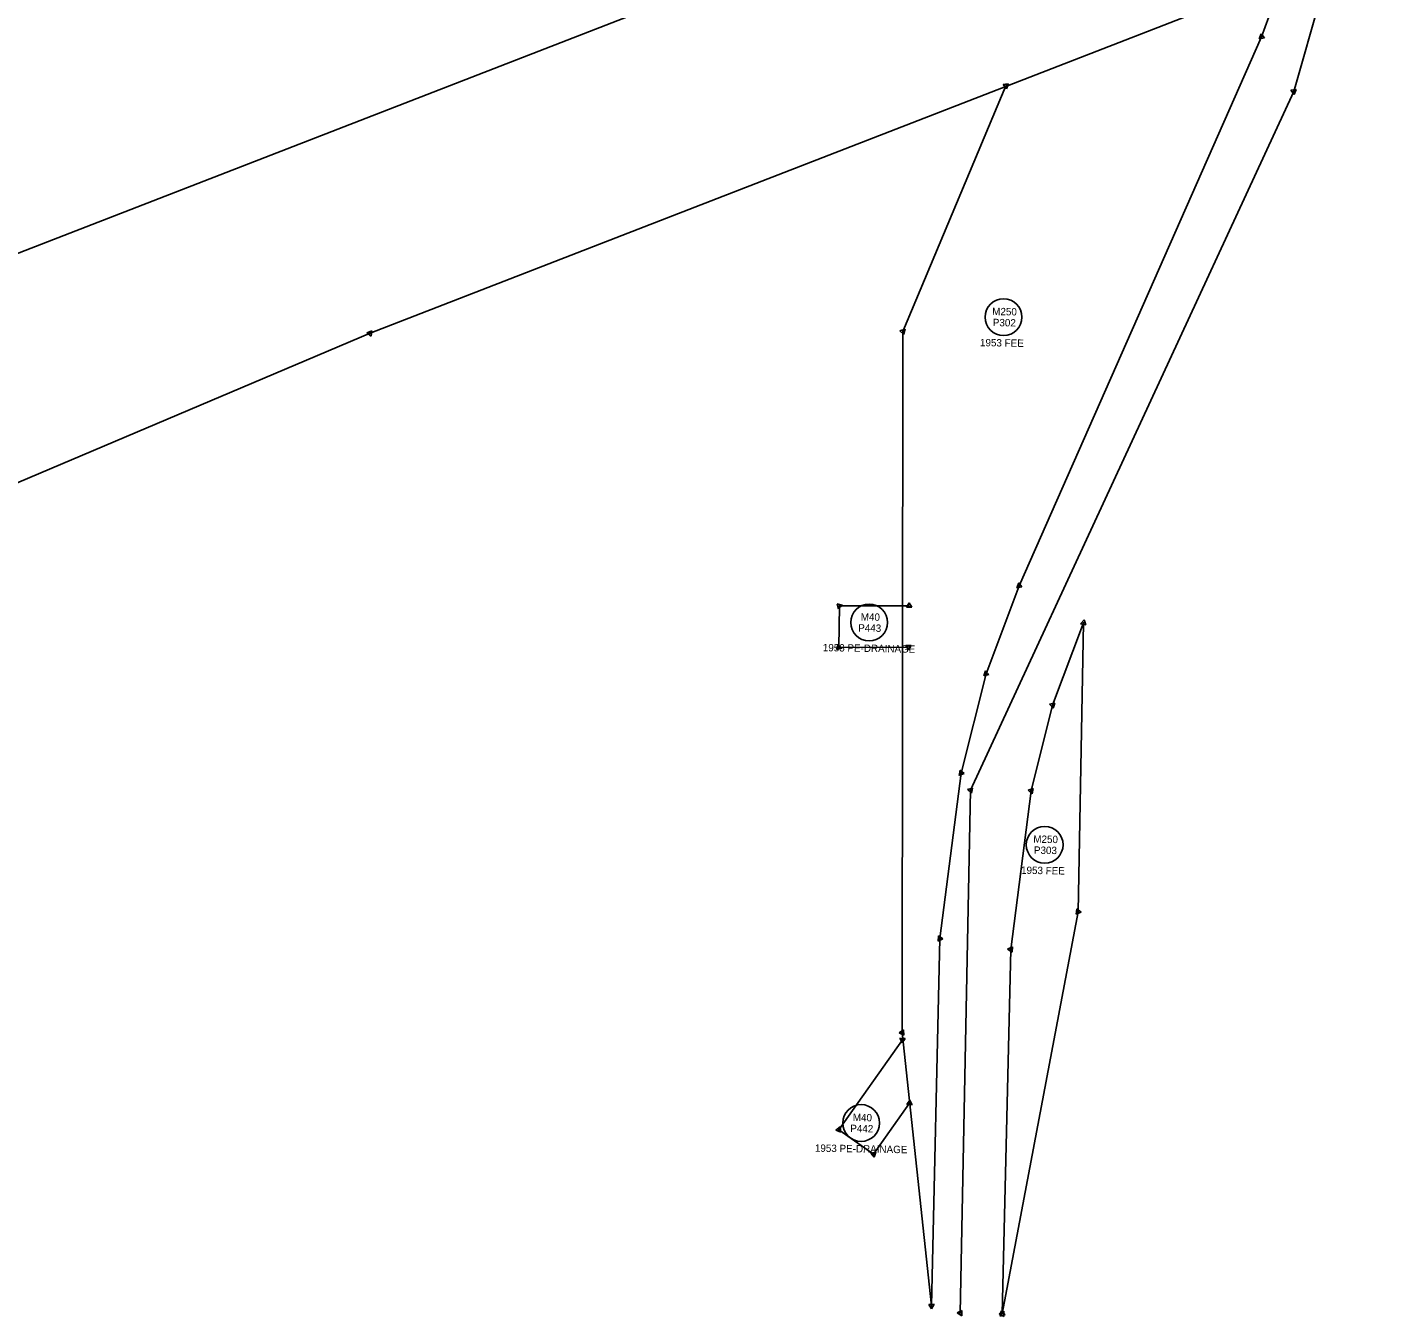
# Model space of a CAD drawing. Extents: x 325018 to 414989, y 1517547 to 1550415.
# Drawn here: x 389679 to 390658, y 1519044 to 1519963 of the extents above; entities that cross this region are included whole.
import ezdxf

# ---------------------------------------------------------------- set-up
doc = ezdxf.new("R2010")
doc.units = 0
for name, color, linetype in [('Level 56', 7, 'Continuous'), ('MEE', 7, 'Continuous'), ('MHB', 7, 'Continuous'), ('MHBWOA', 7, 'Continuous'), ('MRBL1', 7, 'Continuous'), ('MRBL2', 7, 'Continuous')]:
    doc.layers.add(name, color=color, linetype=linetype)

msp = doc.modelspace()

# ---------------------------------------------------------------- linework, layer by layer
at = {"layer": 'Level 56'}
for centre in [(390374.96, 1519756.85), (390279.09, 1519539.04), (390404.25, 1519380.53), (390273.44, 1519182.07)]:
    msp.add_circle(centre, 13.12, dxfattribs=at)
at = {"layer": 'MEE'}
for p, q in [((390257.53, 1519521.27), (390257.96, 1519550.82)), ((390257.96, 1519550.82), (390307.62, 1519551)), ((390307.19, 1519521.46), (390257.53, 1519521.27)), ((390257.64, 1519177.28), (390302.91, 1519241.39)), ((390308.02, 1519196.28), (390282.29, 1519159.79)), ((390282.29, 1519159.79), (390257.64, 1519177.28))]:
    msp.add_line(p, q, dxfattribs=at)
for points in [[(390257.39, 1519548.71), (390256.43, 1519552.37)], [(390256.43, 1519552.37), (390260.08, 1519551.37)], [(390260.08, 1519551.37), (390257.39, 1519548.71)], [(390305.74, 1519549.9), (390307.61, 1519553.18)], [(390309.51, 1519549.91), (390305.74, 1519549.9)], [(390307.61, 1519553.18), (390309.51, 1519549.91)], [(390255.98, 1519519.74), (390256.98, 1519523.39)], [(390259.63, 1519520.7), (390255.98, 1519519.74)], [(390256.98, 1519523.39), (390259.63, 1519520.7)], [(390305.29, 1519522.54), (390309.07, 1519522.56)], [(390307.19, 1519519.28), (390305.29, 1519522.54)], [(390309.07, 1519522.56), (390307.19, 1519519.28)], [(390302.71, 1519239.22), (390301.13, 1519242.65)], [(390301.13, 1519242.65), (390304.89, 1519242.31)], [(390304.89, 1519242.31), (390302.71, 1519239.22)], [(390306.04, 1519195.37), (390308.21, 1519198.46)], [(390309.8, 1519195.03), (390306.04, 1519195.37)], [(390308.21, 1519198.46), (390309.8, 1519195.03)], [(390255.49, 1519176.91), (390258.39, 1519179.32)], [(390259.03, 1519175.6), (390255.49, 1519176.91)], [(390258.39, 1519179.32), (390259.03, 1519175.6)], [(390280.25, 1519160.54), (390283.97, 1519161.18)], [(390282.66, 1519157.64), (390280.25, 1519160.54)], [(390283.97, 1519161.18), (390282.66, 1519157.64)]]:
    msp.add_lwpolyline(points, dxfattribs=at)
for centre, radius in [((390257.96, 1519550.82), 0.227), ((390307.62, 1519551), 1.09), ((390257.53, 1519521.27), 0.227), ((390307.18, 1519521.46), 1.09), ((390302.91, 1519241.4), 1.09), ((390308.02, 1519196.28), 1.09), ((390257.64, 1519177.28), 0.227), ((390282.29, 1519159.79), 0.227)]:
    msp.add_circle(centre, radius, dxfattribs=at)
at = {"layer": 'MHB'}
for p, q in [((390573.98, 1519998.09), (390558.88, 1519956.76)), ((390558.88, 1519956.76), (390386.02, 1519565.22)), ((390303.25, 1519746.6), (390376.69, 1519921.84)), ((390302.64, 1519246.6), (390303.25, 1519746.6)), ((390386.02, 1519565.22), (390362.48, 1519502.49)), ((390409.89, 1519480.06), (390431.94, 1519538.71)), ((390431.94, 1519538.71), (390428.06, 1519332.74)), ((390362.48, 1519502.49), (390344.74, 1519431.68)), ((390394.58, 1519418.95), (390409.89, 1519480.06)), ((390344.74, 1519431.68), (390329.58, 1519313.65)), ((390380.05, 1519305.88), (390394.58, 1519418.95)), ((390428.06, 1519332.74), (390374.06, 1519045.95)), ((390329.58, 1519313.65), (390323.54, 1519051.72)), ((390374.06, 1519045.95), (390380.05, 1519305.88)), ((390323.54, 1519051.72), (390302.64, 1519246.6))]:
    msp.add_line(p, q, dxfattribs=at)
for points in [[(390557.16, 1519955.42), (390558.57, 1519958.92)], [(390558.57, 1519958.92), (390560.9, 1519955.95)], [(390560.9, 1519955.95), (390557.16, 1519955.42)], [(390374.68, 1519922.68), (390378.43, 1519923.16)], [(390376.97, 1519919.67), (390374.68, 1519922.68)], [(390378.43, 1519923.16), (390376.97, 1519919.67)], [(390301.12, 1519747.03), (390304.7, 1519748.24)], [(390303.95, 1519744.53), (390301.12, 1519747.03)], [(390304.7, 1519748.24), (390303.95, 1519744.53)], [(390384.3, 1519563.88), (390385.73, 1519567.38)], [(390385.73, 1519567.38), (390388.04, 1519564.4)], [(390388.04, 1519564.4), (390384.3, 1519563.88)], [(390429.87, 1519537.99), (390432.34, 1519540.85)], [(390433.59, 1519537.28), (390429.87, 1519537.99)], [(390432.34, 1519540.85), (390433.59, 1519537.28)], [(390360.88, 1519501.01), (390362, 1519504.62)], [(390364.56, 1519501.84), (390360.88, 1519501.01)], [(390362, 1519504.62), (390364.56, 1519501.84)], [(390407.82, 1519480.71), (390411.5, 1519481.54)], [(390410.38, 1519477.93), (390407.82, 1519480.71)], [(390411.5, 1519481.54), (390410.38, 1519477.93)], [(390343.31, 1519430.03), (390344.01, 1519433.74)], [(390346.88, 1519431.28), (390343.31, 1519430.03)], [(390344.01, 1519433.74), (390346.88, 1519431.28)], [(390392.44, 1519419.36), (390396, 1519420.61)], [(390395.3, 1519416.89), (390392.44, 1519419.36)], [(390396, 1519420.61), (390395.3, 1519416.89)], [(390426.78, 1519330.98), (390427.16, 1519334.74)], [(390430.22, 1519332.52), (390426.78, 1519330.98)], [(390427.16, 1519334.74), (390430.22, 1519332.52)], [(390328.34, 1519311.85), (390328.63, 1519315.62)], [(390331.75, 1519313.49), (390328.34, 1519311.85)], [(390328.63, 1519315.62), (390331.75, 1519313.49)], [(390377.88, 1519306.05), (390381.29, 1519307.68)], [(390381, 1519303.92), (390377.88, 1519306.05)], [(390381.29, 1519307.68), (390381, 1519303.92)], [(390300.47, 1519246.49), (390303.64, 1519248.55)], [(390303.83, 1519244.77), (390300.47, 1519246.49)], [(390303.64, 1519248.55), (390303.83, 1519244.77)], [(390321.61, 1519052.73), (390325.38, 1519052.89)], [(390323.63, 1519049.54), (390321.61, 1519052.73)], [(390325.38, 1519052.89), (390323.63, 1519049.54)], [(390371.89, 1519046), (390375.2, 1519047.81)], [(390375.11, 1519044.04), (390371.89, 1519046)], [(390372.64, 1519044.3), (390373.34, 1519048.01)], [(390373.34, 1519048.01), (390376.2, 1519045.55)], [(390375.2, 1519047.81), (390375.11, 1519044.04)], [(390376.2, 1519045.55), (390372.64, 1519044.3)]]:
    msp.add_lwpolyline(points, dxfattribs=at)
for centre, radius in [((390558.88, 1519956.76), 0.227), ((390376.69, 1519921.84), 1.09), ((390303.25, 1519746.6), 0.227), ((390386.02, 1519565.22), 0.227), ((390431.94, 1519538.71), 0.227), ((390362.48, 1519502.49), 0.227), ((390409.89, 1519480.06), 0.227), ((390344.74, 1519431.68), 0.227), ((390394.58, 1519418.95), 0.227), ((390428.06, 1519332.74), 0.227), ((390329.58, 1519313.65), 0.227), ((390380.05, 1519305.88), 0.227), ((390302.64, 1519246.6), 0.227), ((390323.54, 1519051.72), 0.227), ((390374.06, 1519045.95), 1.09), ((390374.06, 1519045.95), 1.09)]:
    msp.add_circle(centre, radius, dxfattribs=at)
at = {"layer": 'MHBWOA'}
for p, q in [((390573.98, 1519998.09), (389923.35, 1519745.33)), ((389923.35, 1519745.33), (389462.55, 1519549.87))]:
    msp.add_line(p, q, dxfattribs=at)
for points in [[(389921.19, 1519745.64), (389924.69, 1519747.06)], [(389924.17, 1519743.32), (389921.19, 1519745.64)], [(389924.69, 1519747.06), (389924.17, 1519743.32)]]:
    msp.add_lwpolyline(points, dxfattribs=at)
msp.add_circle((389923.35, 1519745.33), 0.227, dxfattribs=at)
at = {"layer": 'MRBL1'}
msp.add_line((389440.86, 1519712.45), (390657.94, 1520185.18), dxfattribs=at)
at = {"layer": 'MRBL2'}
for p, q in [((390581.83, 1519917.84), (390657.94, 1520185.18)), ((390351.43, 1519419.36), (390581.83, 1519917.84)), ((390344.07, 1519046.54), (390351.43, 1519419.36))]:
    msp.add_line(p, q, dxfattribs=at)
for points in [[(390579.79, 1519918.6), (390583.52, 1519919.23)], [(390582.2, 1519915.69), (390579.79, 1519918.6)], [(390583.52, 1519919.23), (390582.2, 1519915.69)], [(390349.31, 1519419.85), (390352.92, 1519420.96)], [(390352.08, 1519417.27), (390349.31, 1519419.85)], [(390352.92, 1519420.96), (390352.08, 1519417.27)], [(390341.89, 1519046.59), (390345.2, 1519048.41)], [(390345.13, 1519044.63), (390341.89, 1519046.59)], [(390345.2, 1519048.41), (390345.13, 1519044.63)]]:
    msp.add_lwpolyline(points, dxfattribs=at)
for centre, radius in [((390581.83, 1519917.84), 0.227), ((390351.43, 1519419.36), 0.227), ((390344.07, 1519046.55), 1.09)]:
    msp.add_circle(centre, radius, dxfattribs=at)

# ---------------------------------------------------------------- texts
at = {"layer": 'Level 56'}
for s, height, p in [('M250', 5.249, (390366.84, 1519758.3)), ('P302', 5.249, (390367.26, 1519750.42)), ('1953 FEE', 5.249, (390358.11, 1519736.13)), ('M40', 5.249, (390273.13, 1519540.46)), ('P443', 5.249, (390271.32, 1519532.61)), ('1953 PE-DRAINAGE', 5.2493, (390246.08, 1519518.6)), ('M250', 5.249, (390396.13, 1519381.99)), ('P303', 5.249, (390396.57, 1519374.11)), ('1953 FEE', 5.249, (390387.4, 1519359.81)), ('M40', 5.249, (390267.48, 1519183.49)), ('P442', 5.249, (390265.65, 1519175.65)), ('1953 PE-DRAINAGE', 5.2493, (390240.43, 1519161.63))]:
    msp.add_text(s, height=height, rotation=358.99866, dxfattribs=at).set_placement(p)

doc.saveas('drawing.dxf')
